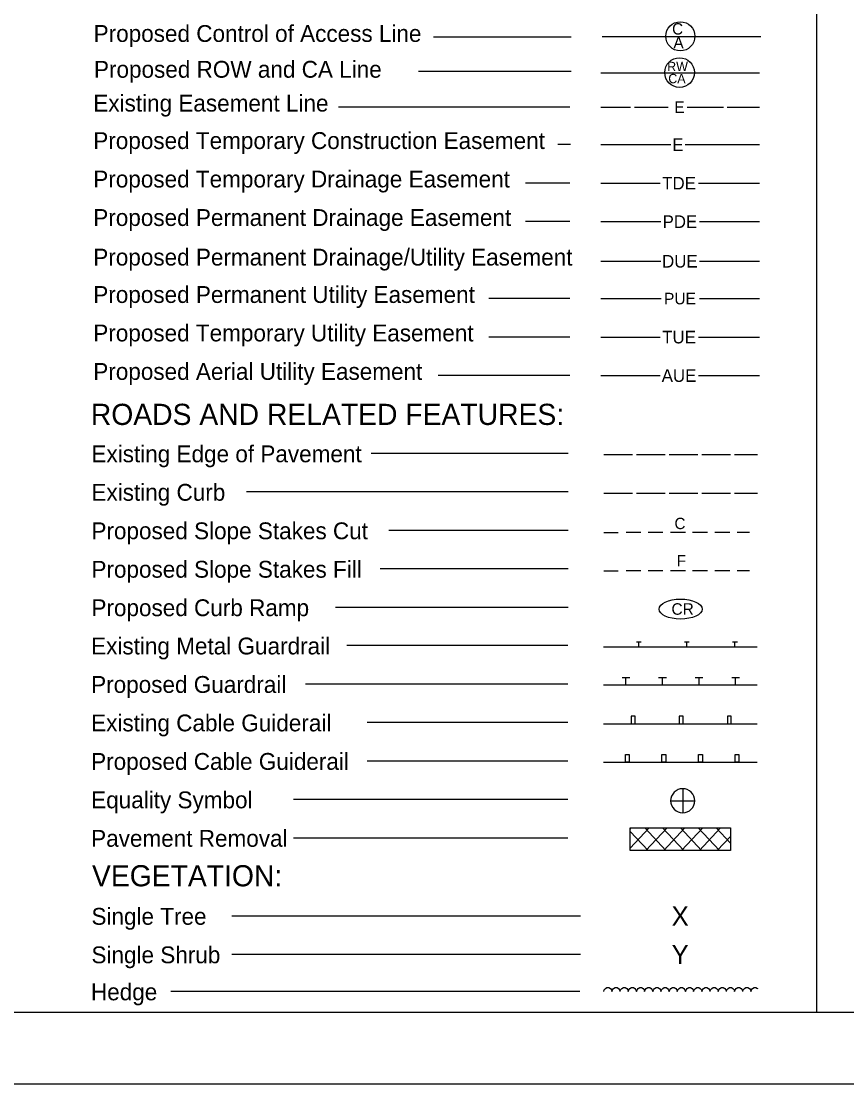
# Model space of a CAD drawing. Extents: x 1855058 to 1858918, y 1540202 to 1542502.
# Drawn here: x 1857552 to 1857985, y 1540202 to 1540759 of the extents above; entities that cross this region are included whole.
import ezdxf

# ---------------------------------------------------------------- set-up
doc = ezdxf.new("R2010")
doc.units = 0
doc.layers.add('CTL Secondary Horizontal and Vertical CELL', color=7, linetype='Continuous')

msp = doc.modelspace()

# ---------------------------------------------------------------- linework, layer by layer
at = {"layer": 'CTL Secondary Horizontal and Vertical CELL'}
for p, q in [((1857968.6, 1541264.27), (1857968.58, 1540239.27)), ((1857840.04, 1540750.58), (1857767.75, 1540750.58)), ((1857856.22, 1540750.96), (1857939.45, 1540750.96)), ((1857839.94, 1540732.66), (1857759.87, 1540732.66)), ((1857855.48, 1540731.88), (1857938.72, 1540731.88)), ((1857839.3, 1540713.88), (1857717.94, 1540713.88)), ((1857855.47, 1540713.88), (1857871.12, 1540713.88)), ((1857873.14, 1540713.88), (1857890.8, 1540713.88)), ((1857900.89, 1540713.88), (1857919.81, 1540713.88)), ((1857921.82, 1540713.88), (1857938.71, 1540713.88)), ((1857839.69, 1540694.25), (1857832.95, 1540694.25)), ((1857855.47, 1540694.25), (1857858.11, 1540694.25)), ((1857858.11, 1540694.25), (1857892.16, 1540694.25)), ((1857899.73, 1540694.25), (1857933.78, 1540694.25)), ((1857933.78, 1540694.25), (1857938.71, 1540694.25)), ((1857839.3, 1540674.07), (1857815.94, 1540674.07)), ((1857855.47, 1540674.07), (1857858.85, 1540674.07)), ((1857858.85, 1540674.07), (1857886.6, 1540674.07)), ((1857906.78, 1540674.07), (1857934.52, 1540674.07)), ((1857934.52, 1540674.07), (1857938.71, 1540674.07)), ((1857839.3, 1540653.89), (1857815.94, 1540653.89)), ((1857855.47, 1540653.89), (1857859.31, 1540653.89)), ((1857859.31, 1540653.89), (1857887.05, 1540653.89)), ((1857907.23, 1540653.89), (1857934.98, 1540653.89)), ((1857934.98, 1540653.89), (1857938.71, 1540653.89)), ((1857855.47, 1540633.13), (1857887.05, 1540633.13)), ((1857907.23, 1540633.13), (1857938.71, 1540633.13)), ((1857839.3, 1540613.53), (1857796.79, 1540613.53)), ((1857855.47, 1540613.53), (1857859.35, 1540613.53)), ((1857859.35, 1540613.53), (1857887.09, 1540613.53)), ((1857907.27, 1540613.53), (1857935.02, 1540613.53)), ((1857935.02, 1540613.53), (1857938.71, 1540613.53)), ((1857839.3, 1540593.35), (1857796.79, 1540593.35)), ((1857855.47, 1540593.35), (1857858.85, 1540593.35)), ((1857858.85, 1540593.35), (1857886.6, 1540593.35)), ((1857906.78, 1540593.35), (1857934.52, 1540593.35)), ((1857934.52, 1540593.35), (1857938.71, 1540593.35)), ((1857839.3, 1540573.17), (1857770.23, 1540573.17)), ((1857855.47, 1540573.17), (1857858.85, 1540573.17)), ((1857858.85, 1540573.17), (1857886.6, 1540573.17)), ((1857906.78, 1540573.17), (1857934.52, 1540573.17)), ((1857934.52, 1540573.17), (1857938.71, 1540573.17)), ((1857838.33, 1540532.28), (1857735.07, 1540532.28)), ((1857857.03, 1540531.7), (1857872.16, 1540531.7)), ((1857874.18, 1540531.7), (1857889.31, 1540531.7)), ((1857891.33, 1540531.7), (1857906.46, 1540531.7)), ((1857908.48, 1540531.7), (1857923.62, 1540531.7)), ((1857925.63, 1540531.7), (1857937.74, 1540531.7)), ((1857838.33, 1540512.1), (1857669.69, 1540512.1)), ((1857857.03, 1540511.52), (1857872.16, 1540511.52)), ((1857874.18, 1540511.52), (1857889.31, 1540511.52)), ((1857891.33, 1540511.52), (1857906.46, 1540511.52)), ((1857908.48, 1540511.52), (1857923.62, 1540511.52)), ((1857925.63, 1540511.52), (1857937.74, 1540511.52)), ((1857838.33, 1540491.92), (1857744.31, 1540491.92)), ((1857857.03, 1540490.86), (1857864.69, 1540490.86)), ((1857876.5, 1540490.86), (1857868.88, 1540490.86)), ((1857888.1, 1540490.86), (1857880.43, 1540490.86)), ((1857899.96, 1540490.86), (1857892.09, 1540490.86)), ((1857911.51, 1540490.86), (1857903.69, 1540490.86)), ((1857923.16, 1540490.86), (1857915.24, 1540490.86)), ((1857933.55, 1540490.86), (1857927.1, 1540490.86)), ((1857838.33, 1540471.75), (1857739.72, 1540471.75)), ((1857857.03, 1540470.69), (1857864.69, 1540470.69)), ((1857876.5, 1540470.69), (1857868.88, 1540470.69)), ((1857888.1, 1540470.69), (1857880.43, 1540470.69)), ((1857899.96, 1540470.69), (1857892.09, 1540470.69)), ((1857911.51, 1540470.69), (1857903.69, 1540470.69)), ((1857923.16, 1540470.69), (1857915.24, 1540470.69)), ((1857933.55, 1540470.69), (1857927.1, 1540470.69)), ((1857838.33, 1540451.57), (1857716.32, 1540451.57)), ((1857838.17, 1540431.51), (1857722.31, 1540431.51)), ((1857856.87, 1540430.93), (1857937.58, 1540430.93)), ((1857874.16, 1540433.45), (1857876.68, 1540433.45)), ((1857875.42, 1540430.93), (1857875.42, 1540433.45)), ((1857899.38, 1540433.45), (1857901.9, 1540433.45)), ((1857900.64, 1540430.93), (1857900.64, 1540433.45)), ((1857924.61, 1540433.45), (1857927.13, 1540433.45)), ((1857925.87, 1540430.93), (1857925.87, 1540433.45)), ((1857866.68, 1540414.74), (1857870.72, 1540414.74)), ((1857868.7, 1540410.75), (1857868.7, 1540414.74)), ((1857885.85, 1540414.74), (1857889.89, 1540414.74)), ((1857887.87, 1540410.75), (1857887.87, 1540414.74)), ((1857905.02, 1540414.74), (1857909.06, 1540414.74)), ((1857907.04, 1540410.75), (1857907.04, 1540414.74)), ((1857924.19, 1540414.74), (1857928.22, 1540414.74)), ((1857926.21, 1540410.75), (1857926.21, 1540414.74)), ((1857838.17, 1540411.33), (1857700.72, 1540411.33)), ((1857937.58, 1540410.75), (1857856.87, 1540410.75)), ((1857838.17, 1540391.15), (1857732.94, 1540391.15)), ((1857856.87, 1540390.57), (1857937.58, 1540390.57)), ((1857838.17, 1540370.97), (1857732.94, 1540370.97)), ((1857856.87, 1540370.39), (1857937.58, 1540370.39)), ((1857898.46, 1540356.51), (1857898.46, 1540350.2)), ((1857838.17, 1540350.79), (1857694.27, 1540350.79)), ((1857892.16, 1540350.2), (1857898.46, 1540350.2)), ((1857898.46, 1540350.2), (1857898.46, 1540343.89)), ((1857898.46, 1540350.2), (1857904.77, 1540350.2)), ((1857870.94, 1540335.95), (1857923.51, 1540335.95)), ((1857870.94, 1540324.15), (1857870.94, 1540335.95)), ((1857870.94, 1540335.34), (1857871.5, 1540335.95)), ((1857870.94, 1540325.31), (1857880.88, 1540335.95)), ((1857889.66, 1540324.15), (1857878.56, 1540335.95)), ((1857879.17, 1540324.15), (1857890.26, 1540335.95)), ((1857898.99, 1540324.15), (1857887.94, 1540335.95)), ((1857888.5, 1540324.15), (1857899.65, 1540335.95)), ((1857908.37, 1540324.15), (1857897.28, 1540335.95)), ((1857897.88, 1540324.15), (1857908.98, 1540335.95)), ((1857917.76, 1540324.15), (1857906.61, 1540335.95)), ((1857907.26, 1540324.15), (1857918.31, 1540335.95)), ((1857923.51, 1540327.93), (1857915.99, 1540335.95)), ((1857923.51, 1540335.95), (1857923.51, 1540324.15)), ((1857838.17, 1540330.61), (1857694.27, 1540330.61)), ((1857880.28, 1540324.15), (1857870.94, 1540334.13)), ((1857916.6, 1540324.15), (1857923.51, 1540331.51)), ((1857923.51, 1540324.15), (1857870.94, 1540324.15)), ((1857844.81, 1540289.71), (1857662.07, 1540289.71)), ((1857844.81, 1540269.53), (1857662.07, 1540269.53)), ((1857857.95, 1540251.71), (1857858.76, 1540252.17)), ((1857858.76, 1540252.17), (1857859.72, 1540252.17)), ((1857859.72, 1540252.17), (1857860.52, 1540251.66)), ((1857862.24, 1540251.71), (1857863.05, 1540252.17)), ((1857863.05, 1540252.17), (1857864.01, 1540252.17)), ((1857864.01, 1540252.17), (1857864.81, 1540251.66)), ((1857866.53, 1540251.71), (1857867.34, 1540252.17)), ((1857867.34, 1540252.17), (1857868.29, 1540252.17)), ((1857868.29, 1540252.17), (1857869.1, 1540251.66)), ((1857870.82, 1540251.71), (1857871.62, 1540252.17)), ((1857871.62, 1540252.17), (1857872.58, 1540252.17)), ((1857872.58, 1540252.17), (1857873.39, 1540251.66)), ((1857875.1, 1540251.71), (1857875.91, 1540252.17)), ((1857875.91, 1540252.17), (1857876.87, 1540252.17)), ((1857876.87, 1540252.17), (1857877.68, 1540251.66)), ((1857879.39, 1540251.71), (1857880.2, 1540252.17)), ((1857880.2, 1540252.17), (1857881.16, 1540252.17)), ((1857881.16, 1540252.17), (1857881.96, 1540251.66)), ((1857883.68, 1540251.71), (1857884.49, 1540252.17)), ((1857884.49, 1540252.17), (1857885.45, 1540252.17)), ((1857885.45, 1540252.17), (1857886.25, 1540251.66)), ((1857887.97, 1540251.71), (1857888.78, 1540252.17)), ((1857888.78, 1540252.17), (1857889.73, 1540252.17)), ((1857889.73, 1540252.17), (1857890.54, 1540251.66)), ((1857892.26, 1540251.71), (1857893.06, 1540252.17)), ((1857893.06, 1540252.17), (1857894.02, 1540252.17)), ((1857894.02, 1540252.17), (1857894.83, 1540251.66)), ((1857896.54, 1540251.71), (1857897.35, 1540252.17)), ((1857897.35, 1540252.17), (1857898.31, 1540252.17)), ((1857898.31, 1540252.17), (1857899.12, 1540251.66)), ((1857900.83, 1540251.71), (1857901.64, 1540252.17)), ((1857901.64, 1540252.17), (1857902.6, 1540252.17)), ((1857902.6, 1540252.17), (1857903.4, 1540251.66)), ((1857905.12, 1540251.71), (1857905.93, 1540252.17)), ((1857905.93, 1540252.17), (1857906.89, 1540252.17)), ((1857906.89, 1540252.17), (1857907.69, 1540251.66)), ((1857909.41, 1540251.71), (1857910.22, 1540252.17)), ((1857910.22, 1540252.17), (1857911.17, 1540252.17)), ((1857911.17, 1540252.17), (1857911.98, 1540251.66)), ((1857913.7, 1540251.71), (1857914.5, 1540252.17)), ((1857914.5, 1540252.17), (1857915.46, 1540252.17)), ((1857915.46, 1540252.17), (1857916.27, 1540251.66)), ((1857917.98, 1540251.71), (1857918.79, 1540252.17)), ((1857918.79, 1540252.17), (1857919.75, 1540252.17)), ((1857919.75, 1540252.17), (1857920.56, 1540251.66)), ((1857922.27, 1540251.71), (1857923.08, 1540252.17)), ((1857923.08, 1540252.17), (1857924.04, 1540252.17)), ((1857924.04, 1540252.17), (1857924.84, 1540251.66)), ((1857926.56, 1540251.71), (1857927.37, 1540252.17)), ((1857927.37, 1540252.17), (1857928.33, 1540252.17)), ((1857928.33, 1540252.17), (1857929.13, 1540251.66)), ((1857930.85, 1540251.71), (1857931.66, 1540252.17)), ((1857931.66, 1540252.17), (1857932.61, 1540252.17)), ((1857932.61, 1540252.17), (1857933.42, 1540251.66)), ((1857935.14, 1540251.71), (1857935.94, 1540252.17)), ((1857935.94, 1540252.17), (1857936.9, 1540252.17)), ((1857936.9, 1540252.17), (1857937.71, 1540251.66)), ((1857844.54, 1540250.1), (1857629.95, 1540250.1)), ((1857857.04, 1540250.1), (1857857.35, 1540251.06)), ((1857857.35, 1540251.06), (1857857.95, 1540251.71)), ((1857860.52, 1540251.66), (1857861.08, 1540251.01)), ((1857861.08, 1540251.01), (1857861.28, 1540250.15)), ((1857861.33, 1540250.1), (1857861.63, 1540251.06)), ((1857861.63, 1540251.06), (1857862.24, 1540251.71)), ((1857864.81, 1540251.66), (1857865.37, 1540251.01)), ((1857865.37, 1540251.01), (1857865.57, 1540250.15)), ((1857865.62, 1540250.1), (1857865.92, 1540251.06)), ((1857865.92, 1540251.06), (1857866.53, 1540251.71)), ((1857869.1, 1540251.66), (1857869.66, 1540251.01)), ((1857869.66, 1540251.01), (1857869.86, 1540250.15)), ((1857869.91, 1540250.1), (1857870.21, 1540251.06)), ((1857870.21, 1540251.06), (1857870.82, 1540251.71)), ((1857873.39, 1540251.66), (1857873.94, 1540251.01)), ((1857873.94, 1540251.01), (1857874.15, 1540250.15)), ((1857874.2, 1540250.1), (1857874.5, 1540251.06)), ((1857874.5, 1540251.06), (1857875.1, 1540251.71)), ((1857877.68, 1540251.66), (1857878.23, 1540251.01)), ((1857878.23, 1540251.01), (1857878.43, 1540250.15)), ((1857878.48, 1540250.1), (1857878.79, 1540251.06)), ((1857878.79, 1540251.06), (1857879.39, 1540251.71)), ((1857881.96, 1540251.66), (1857882.52, 1540251.01)), ((1857882.52, 1540251.01), (1857882.72, 1540250.15)), ((1857882.77, 1540250.1), (1857883.07, 1540251.06)), ((1857883.07, 1540251.06), (1857883.68, 1540251.71)), ((1857886.25, 1540251.66), (1857886.81, 1540251.01)), ((1857886.81, 1540251.01), (1857887.01, 1540250.15)), ((1857887.06, 1540250.1), (1857887.36, 1540251.06)), ((1857887.36, 1540251.06), (1857887.97, 1540251.71)), ((1857890.54, 1540251.66), (1857891.1, 1540251.01)), ((1857891.1, 1540251.01), (1857891.3, 1540250.15)), ((1857891.35, 1540250.1), (1857891.65, 1540251.06)), ((1857891.65, 1540251.06), (1857892.26, 1540251.71)), ((1857894.83, 1540251.66), (1857895.38, 1540251.01)), ((1857895.38, 1540251.01), (1857895.59, 1540250.15)), ((1857895.64, 1540250.1), (1857895.94, 1540251.06)), ((1857895.94, 1540251.06), (1857896.54, 1540251.71)), ((1857899.12, 1540251.66), (1857899.67, 1540251.01)), ((1857899.67, 1540251.01), (1857899.87, 1540250.15)), ((1857899.92, 1540250.1), (1857900.23, 1540251.06)), ((1857900.23, 1540251.06), (1857900.83, 1540251.71)), ((1857903.4, 1540251.66), (1857903.96, 1540251.01)), ((1857903.96, 1540251.01), (1857904.16, 1540250.15)), ((1857904.21, 1540250.1), (1857904.51, 1540251.06)), ((1857904.51, 1540251.06), (1857905.12, 1540251.71)), ((1857907.69, 1540251.66), (1857908.25, 1540251.01)), ((1857908.25, 1540251.01), (1857908.45, 1540250.15)), ((1857908.5, 1540250.1), (1857908.8, 1540251.06)), ((1857908.8, 1540251.06), (1857909.41, 1540251.71)), ((1857911.98, 1540251.66), (1857912.54, 1540251.01)), ((1857912.54, 1540251.01), (1857912.74, 1540250.15)), ((1857912.79, 1540250.1), (1857913.09, 1540251.06)), ((1857913.09, 1540251.06), (1857913.7, 1540251.71)), ((1857916.27, 1540251.66), (1857916.82, 1540251.01)), ((1857916.82, 1540251.01), (1857917.03, 1540250.15)), ((1857917.08, 1540250.1), (1857917.38, 1540251.06)), ((1857917.38, 1540251.06), (1857917.98, 1540251.71)), ((1857920.56, 1540251.66), (1857921.11, 1540251.01)), ((1857921.11, 1540251.01), (1857921.31, 1540250.15)), ((1857921.36, 1540250.1), (1857921.67, 1540251.06)), ((1857921.67, 1540251.06), (1857922.27, 1540251.71)), ((1857924.84, 1540251.66), (1857925.4, 1540251.01)), ((1857925.4, 1540251.01), (1857925.6, 1540250.15)), ((1857925.65, 1540250.1), (1857925.95, 1540251.06)), ((1857925.95, 1540251.06), (1857926.56, 1540251.71)), ((1857929.13, 1540251.66), (1857929.69, 1540251.01)), ((1857929.69, 1540251.01), (1857929.89, 1540250.15)), ((1857929.94, 1540250.1), (1857930.24, 1540251.06)), ((1857930.24, 1540251.06), (1857930.85, 1540251.71)), ((1857933.42, 1540251.66), (1857933.98, 1540251.01)), ((1857933.98, 1540251.01), (1857934.18, 1540250.15)), ((1857934.23, 1540250.1), (1857934.53, 1540251.06)), ((1857934.53, 1540251.06), (1857935.14, 1540251.71)), ((1857937.71, 1540251.66), (1857937.76, 1540251.61)), ((1857156.1, 1540239.27), (1858781.08, 1540239.27)), ((1857118.6, 1540201.77), (1858818.6, 1540201.77))]:
    msp.add_line(p, q, dxfattribs=at)
for points in [[(1857871.47, 1540390.57), (1857873.49, 1540390.57), (1857873.49, 1540394.61), (1857871.47, 1540394.61)], [(1857896.7, 1540390.57), (1857898.71, 1540390.57), (1857898.71, 1540394.61), (1857896.7, 1540394.61)], [(1857921.92, 1540390.57), (1857923.94, 1540390.57), (1857923.94, 1540394.61), (1857921.92, 1540394.61)], [(1857868.43, 1540374.43), (1857870.45, 1540374.43), (1857870.45, 1540370.39), (1857868.43, 1540370.39)], [(1857887.6, 1540374.43), (1857889.62, 1540374.43), (1857889.62, 1540370.39), (1857887.6, 1540370.39)], [(1857906.77, 1540374.43), (1857908.79, 1540374.43), (1857908.79, 1540370.39), (1857906.77, 1540370.39)], [(1857925.94, 1540374.43), (1857927.96, 1540374.43), (1857927.96, 1540370.39), (1857925.94, 1540370.39)]]:
    msp.add_lwpolyline(points, close=True, dxfattribs=at)
for centre, radius in [((1857897.23, 1540751.07), 7.65), ((1857896.84, 1540732.04), 7.79)]:
    msp.add_circle(centre, radius, dxfattribs=at)
for start, end in [(89.9944, 179.9989), (359.9944, 89.9989), (179.9944, 269.9989), (269.9944, 359.9989)]:
    msp.add_arc((1857898.46, 1540350.2), 6.31, start, end, dxfattribs=at)
msp.add_ellipse((1857897.35, 1540450.69), major_axis=(11.31, 0), ratio=0.462467, dxfattribs=at)

# ---------------------------------------------------------------- texts
for s, height, p in [('Proposed Control of Access Line', 8.8282, (1857589.53, 1540748.13)), ('C', 5.99, (1857892.9, 1540751.97)), ('A', 5.99, (1857893.61, 1540744.77)), ('Proposed ROW and CA Line', 8.8282, (1857589.7, 1540729.35)), ('RW', 4.882, (1857890.33, 1540732.81)), ('CA', 4.882, (1857890.9, 1540726.47)), ('Existing Easement Line', 8.8282, (1857589.34, 1540711.6)), ('E', 6.05, (1857894.03, 1540710.85)), ('Proposed Temporary Construction Easement', 8.8282, (1857589.34, 1540691.97)), ('E', 6.61, (1857893.02, 1540690.92)), ('Proposed Temporary Drainage Easement', 8.8282, (1857589.34, 1540671.79)), ('TDE', 6.608, (1857887.72, 1540670.74)), ('Proposed Permanent Drainage Easement', 8.8282, (1857589.34, 1540651.61)), ('PDE', 6.608, (1857887.91, 1540650.56)), ('Proposed Permanent Drainage/Utility Easement', 8.8282, (1857589.34, 1540630.85)), ('DUE', 6.608, (1857887.66, 1540629.8)), ('Proposed Permanent Utility Easement', 8.8282, (1857589.34, 1540611.24)), ('PUE', 6.054, (1857888.71, 1540610.5)), ('Proposed Temporary Utility Easement', 8.8282, (1857589.34, 1540591.07)), ('TUE', 6.608, (1857887.72, 1540590.02)), ('Proposed Aerial Utility Easement', 8.8282, (1857589.34, 1540570.89)), ('AUE', 6.608, (1857887.46, 1540569.84)), ('ROADS AND RELATED FEATURES:', 11.0983, (1857588.06, 1540547.26)), ('Existing Edge of Pavement', 8.8282, (1857588.37, 1540527.69)), ('Existing Curb', 8.8282, (1857588.37, 1540507.51)), ('C', 5.98, (1857894.15, 1540492.62)), ('Proposed Slope Stakes Cut', 8.8282, (1857588.37, 1540487.33)), ('Proposed Slope Stakes Fill', 8.8282, (1857588.37, 1540467.15)), ('F', 5.98, (1857895.37, 1540473.07)), ('Proposed Curb Ramp', 8.8282, (1857588.37, 1540446.98)), ('CR', 6.054, (1857892.59, 1540447.71)), ('Existing Metal Guardrail', 8.8282, (1857588.21, 1540426.92)), ('Proposed Guardrail', 8.8282, (1857588.22, 1540406.75)), ('Existing Cable Guiderail', 8.8282, (1857588.22, 1540386.57)), ('Proposed Cable Guiderail', 8.8282, (1857588.22, 1540366.39)), ('Equality Symbol', 8.8282, (1857588.22, 1540346.22)), ('Pavement Removal', 8.8282, (1857588.22, 1540326.04)), ('VEGETATION:', 11.0983, (1857588.65, 1540305.3)), ('Single Tree', 8.8282, (1857588.38, 1540285.14)), ('X', 10.09, (1857892.63, 1540284.66)), ('Y', 10.09, (1857892.63, 1540264.49)), ('Single Shrub', 8.8282, (1857588.38, 1540264.96)), ('Hedge', 8.828, (1857588.11, 1540245.53))]:
    msp.add_text(s, height=height, dxfattribs=at).set_placement(p)

doc.saveas('drawing.dxf')
